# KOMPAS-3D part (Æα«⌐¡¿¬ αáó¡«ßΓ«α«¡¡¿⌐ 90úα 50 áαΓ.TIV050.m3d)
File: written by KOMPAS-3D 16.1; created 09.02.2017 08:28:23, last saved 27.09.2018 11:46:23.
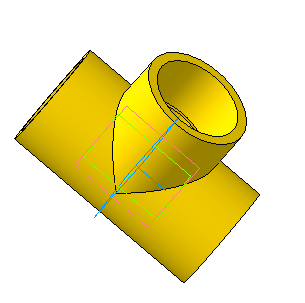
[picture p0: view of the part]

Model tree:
1. Эскиз:1
2. Операция выдавливания:9
     Расстояние 1 = 58
3. Массив по концентрической сетке:1  (with: Операция выдавливания:9, Эскиз:1)  (3 pattern instances)
     Геометрический массив = 2; Шаг 2 = 180
4. Эскиз:20
5. Вырезать элемент выдавливания:6
     Расстояние 1 = 116
6. Эскиз:21
7. Вырезать элемент выдавливания:7
     Расстояние 1 = 58
8. Эскиз:22
9. Вырезать элемент выдавливания:8
     Расстояние 1 = 31
10. Массив по концентрической сетке:3  (with: Вырезать элемент выдавливания:8, Эскиз:22)  (labels: Полипропилен  ГОСТ 26996-86)  (3 pattern instances)
     Геометрический массив = 2; Шаг 2 = 180

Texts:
  Тройник равносторонний ПВХ 90гр 50 арт.TIV050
